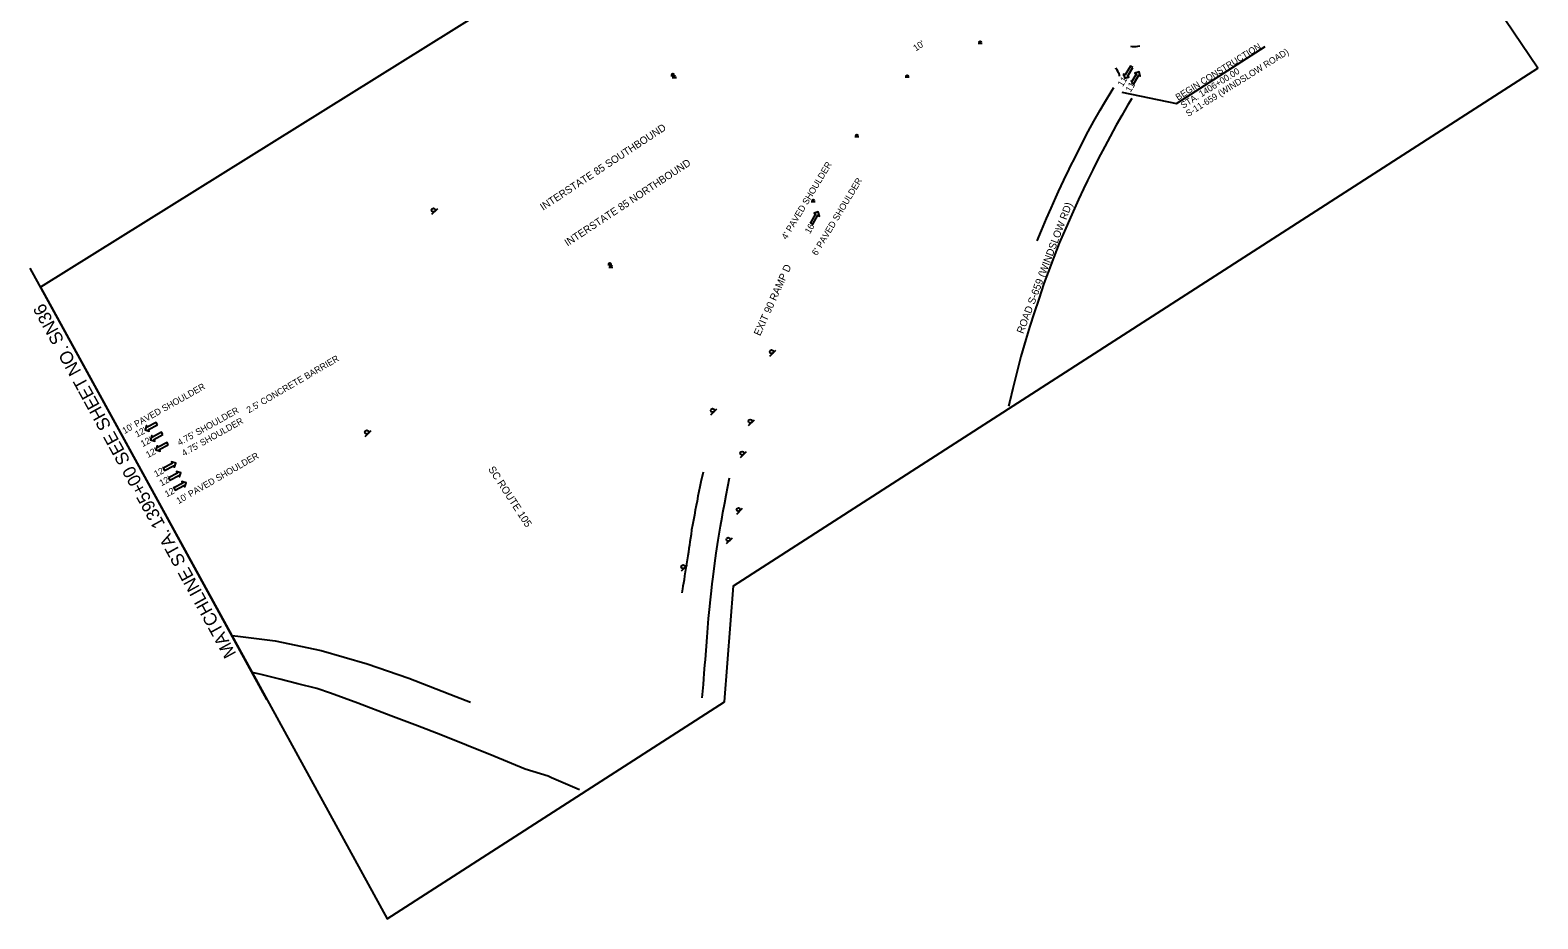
# Model space of a CAD drawing. Extents: x 1788362 to 1789997, y 1182358 to 1184055.
# Drawn here: x 1788362 to 1789997, y 1182358 to 1183321 of the extents above; entities that cross this region are included whole.
import ezdxf

# ---------------------------------------------------------------- set-up
doc = ezdxf.new("R2010")
doc.units = 0
for name, color, linetype in [('RD_EX_Road', 7, 'Continuous'), ('RD_PD_Final_LnLine', 7, 'Continuous'), ('RD_PD_Final_TX', 7, 'Continuous'), ('RD_SHT_MatchLine', 7, 'Continuous'), ('RD_SHT_ShtClip', 7, 'Continuous'), ('RD_TX_RoadID', 7, 'Continuous'), ('SN_P_Signs', 7, 'Continuous')]:
    doc.layers.add(name, color=color, linetype=linetype)

# ---------------------------------------------------------------- blocks, each defined once
blk = doc.blocks.new('SARRW2')
at = {"layer": 'RD_PD_Final_LnLine'}
blk.add_lwpolyline([(-12, 1.2), (-12, -1.2), (-2.8, -1.2), (-2.8, -2.8), (0, 0), (-2.8, 2.8), (-2.8, 1.2)], close=True, dxfattribs=at)

msp = doc.modelspace()

# ---------------------------------------------------------------- linework, layer by layer
at = {"layer": 'RD_EX_Road'}
for points in [[(1789554.8, 1183303.5), (1789556.7, 1183303.2), (1789559.2, 1183303), (1789561.1, 1183303.1), (1789563, 1183303.3), (1789565, 1183303.8)], [(1789543.2, 1183271), (1789543, 1183272), (1789542.6, 1183273.4), (1789542, 1183274.6), (1789541.2, 1183276.4), (1789540.2, 1183278), (1789539.1, 1183279.4), (1789538.9, 1183279.5)], [(1789543.2, 1183271), (1789543, 1183272), (1789542.6, 1183273.4), (1789542, 1183274.6), (1789541.2, 1183276.4), (1789540.2, 1183278), (1789539, 1183279.5)], [(1789453.9, 1183092.5), (1789458.4, 1183103.5), (1789463.9, 1183116.7), (1789468.9, 1183128), (1789474, 1183139.4), (1789477, 1183146.1), (1789482.6, 1183158.1), (1789488.5, 1183170.2), (1789489.9, 1183173.3), (1789494.5, 1183182.2), (1789502.2, 1183197.6), (1789509.2, 1183210.9), (1789515.2, 1183222), (1789522.1, 1183234.1), (1789526.7, 1183241.9), (1789535, 1183255.8), (1789536.8, 1183258.8)], [(1789556.4, 1183246.9), (1789552, 1183239.7), (1789545.4, 1183228.4), (1789539.4, 1183217.8), (1789532.8, 1183205.5), (1789527, 1183194.7), (1789520, 1183181.5), (1789514, 1183169.4), (1789508.2, 1183157.7), (1789504, 1183148.9), (1789498.5, 1183137.1), (1789491.4, 1183121.1), (1789484.9, 1183106.3), (1789477.8, 1183089.8), (1789471.9, 1183074.8), (1789465.8, 1183058.6), (1789461.2, 1183046.1), (1789455.5, 1183029.3), (1789450.6, 1183014.5), (1789445.8, 1183000.1), (1789441.4, 1182985.4), (1789436.2, 1182967.1), (1789431.9, 1182949.9), (1789427.4, 1182932.4), (1789424.1, 1182918.7), (1789422.9, 1182913.3)], [(1789091.7, 1182841.8), (1789089.4, 1182831.1), (1789088.3, 1182826), (1789087.2, 1182820.8), (1789086.1, 1182815.6), (1789085.1, 1182810.5), (1789084.1, 1182805.5), (1789083.1, 1182800.4), (1789082.2, 1182795.2), (1789081.2, 1182789.8), (1789080.2, 1182784.3), (1789079.3, 1182779.1), (1789078.6, 1182774.3), (1789077.9, 1182770.1), (1789077.3, 1182766.3), (1789076.8, 1182762.6), (1789076.3, 1182759), (1789075.7, 1182755.1), (1789075.1, 1182751), (1789074.5, 1182746.7), (1789073.8, 1182742.4), (1789073.1, 1182737.9), (1789072.4, 1182733.6), (1789071.7, 1182729.3), (1789071, 1182725.2), (1789070.4, 1182721.5), (1789069.8, 1182718.2), (1789069.4, 1182715.4), (1789068.5, 1182711)], [(1789090.8, 1182597.1), (1789092, 1182611.5), (1789092.5, 1182617.6), (1789092.7, 1182623.6), (1789093.1, 1182628.2), (1789093.7, 1182633.1), (1789094.2, 1182638.2), (1789094.7, 1182643.7), (1789095.4, 1182653.3), (1789096.1, 1182663), (1789096.9, 1182673.1), (1789097.6, 1182683), (1789098.6, 1182693), (1789099.8, 1182703.3), (1789100.7, 1182713.3), (1789101.7, 1182720.7), (1789102.6, 1182728.2), (1789104.5, 1182743.2), (1789105.9, 1182754.1), (1789108.1, 1182768.1), (1789110.6, 1182783.4), (1789112.2, 1182793), (1789113.2, 1182797.9), (1789115.1, 1182808.4), (1789116.7, 1182816.8), (1789120.4, 1182835.6)], [(1788580.9, 1182664.6), (1788587.2, 1182664), (1788627.7, 1182658.9), (1788677.6, 1182648.4), (1788727.6, 1182634.2), (1788772.6, 1182618.4), (1788823.8, 1182598.6), (1788839.5, 1182592.5)], [(1788957.9, 1182497.6), (1788927.4, 1182510.6), (1788923.7, 1182512.2), (1788898.8, 1182519.8), (1788864.7, 1182534), (1788835.4, 1182545.9), (1788807.3, 1182557.1), (1788782.2, 1182566.8), (1788753.4, 1182577.6), (1788717.4, 1182591.3), (1788687.8, 1182602.2), (1788673, 1182607.2), (1788652.5, 1182612.5), (1788632.8, 1182617.5), (1788612.7, 1182622.4), (1788602.9, 1182624.6)]]:
    msp.add_lwpolyline(points, dxfattribs=at)
at = {"layer": 'RD_PD_Final_TX'}
for p, q in [((1789605, 1183241.4), (1789701.1, 1183303.2)), ((1789545.4, 1183253.6), (1789605, 1183241.4))]:
    msp.add_line(p, q, dxfattribs=at)
at = {"layer": 'RD_SHT_MatchLine'}
msp.add_lwpolyline([(1788618.9, 1182595.5), (1788482.6, 1182843.8), (1788362.3, 1183062.9)], dxfattribs=at)
at = {"layer": 'RD_SHT_ShtClip'}
msp.add_lwpolyline([(1789873, 1183462.7), (1789616.4, 1183843.9), (1789510.9, 1184000.6), (1789102.3, 1183737.7), (1789072.3, 1183540), (1788937.1, 1183533.1), (1788932.8, 1183391.2), (1788373.6, 1183042.3), (1788602.9, 1182624.6), (1788749.4, 1182357.6), (1789114.8, 1182592.7), (1789124.7, 1182718.7), (1789996.5, 1183279.6)], close=True, dxfattribs=at)
at = {"layer": 'SN_P_Signs'}
for p, q in [((1789389.8, 1183306.8), (1789394.3, 1183306.8)), ((1789056.7, 1183271.8), (1789061.2, 1183271.8)), ((1789058.2, 1183269.6), (1789062.7, 1183269.6)), ((1789310.7, 1183270.1), (1789315.2, 1183270.1)), ((1789256.1, 1183205.7), (1789260.6, 1183205.7)), ((1788797.7, 1183121.2), (1788804, 1183127.6)), ((1789208.8, 1183135.1), (1789213.3, 1183135.1)), ((1788988.3, 1183066.7), (1788992.8, 1183066.7)), ((1788989.5, 1183064.1), (1788994, 1183064.1)), ((1789164.1, 1182967.6), (1789170.5, 1182973.9)), ((1789100.1, 1182904), (1789106.5, 1182910.3)), ((1789141, 1182892.2), (1789147.4, 1182898.6)), ((1788725.4, 1182880.4), (1788731.8, 1182886.8)), ((1789132.3, 1182857.7), (1789138.6, 1182864)), ((1789128.2, 1182796.4), (1789134.5, 1182802.8)), ((1789117.2, 1182764.3), (1789123.6, 1182770.6)), ((1789068.3, 1182734.7), (1789074.7, 1182741.1))]:
    msp.add_line(p, q, dxfattribs=at)
for centre, radius in [((1789392.1, 1183307.8), 1), ((1789058.9, 1183272.8), 1), ((1789060.5, 1183270.6), 1), ((1789312.9, 1183271.1), 1), ((1789258.4, 1183206.7), 1), ((1788799.4, 1183125.8), 2), ((1789211.1, 1183136.1), 1), ((1788990.5, 1183067.7), 1), ((1788991.8, 1183065.1), 1), ((1789165.9, 1182972.2), 2), ((1789101.9, 1182908.6), 2), ((1789142.8, 1182896.9), 2), ((1788727.2, 1182885.1), 2), ((1789134, 1182862.3), 2), ((1789129.9, 1182801.1), 2), ((1789119, 1182768.9), 2), ((1789070.1, 1182739.3), 2)]:
    msp.add_circle(centre, radius, dxfattribs=at)

# ---------------------------------------------------------------- block references
at = {"layer": 'RD_PD_Final_LnLine'}
for p, xscale, yscale, rotation in [((1789548.7, 1183268.6), 1.1999999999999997, 1.2000000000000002, -121.00059219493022), ((1789564.4, 1183275.5), 1.1999999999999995, 1.2, 58.99940780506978), ((1789216.6, 1183123.8), 1.1999999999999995, 1.2000000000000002, 60.344883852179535), ((1788486.9, 1182887.7), 1.2000000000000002, 1.2000000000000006, -151.9060440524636), ((1788492.7, 1182876.9), 1.2000000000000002, 1.2000000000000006, -151.9060440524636), ((1788498.6, 1182865.9), 1.2000000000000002, 1.2000000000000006, -151.9060440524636), ((1788520, 1182851.6), 1.2, 1.2000000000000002, 28.093955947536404), ((1788525.6, 1182841.1), 1.2, 1.2000000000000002, 28.093955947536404), ((1788531.3, 1182830.3), 1.2, 1.2000000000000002, 28.093955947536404)]:
    msp.add_blockref('SARRW2', p, dxfattribs=dict(at, xscale=xscale, yscale=yscale, rotation=rotation))

# ---------------------------------------------------------------- texts
at = {"layer": 'RD_PD_Final_TX'}
for s, rotation, p in [("10'", 33.9474, (1789322.3, 1183297.6)), ('BEGIN CONSTRUCTION', 32.1266, (1789606.5, 1183244.4)), ('S-11-659 (WINDSLOW ROAD)', 32.1266, (1789617.6, 1183226.7)), ("11'", 58.9994, (1789546.5, 1183258.9)), ('STA. 1406+00.00', 32.1266, (1789612.1, 1183235.6)), ("11'", 58.9994, (1789555, 1183252.9)), ("4' PAVED SHOULDER", 58.9844, (1789182.1, 1183093.3)), ("6' PAVED SHOULDER", 58.9844, (1789215, 1183075.9)), ("16'", 60.3449, (1789207.5, 1183099.5)), ("2.5' CONCRETE BARRIER", 30.2779, (1788599.3, 1182905.4)), ("10' PAVED SHOULDER", 29.3198, (1788464.6, 1182883)), ("4.75' SHOULDER", 29.3198, (1788524.2, 1182870.2)), ("4.75' SHOULDER", 29.3198, (1788529, 1182858.7)), ("12'", 28.094, (1788478.2, 1182879.2)), ("12'", 28.094, (1788484.3, 1182868.9)), ("12'", 28.094, (1788490, 1182857)), ("10' PAVED SHOULDER", 29.9583, (1788523.2, 1182807)), ("12'", 28.094, (1788498.8, 1182836.2)), ("12'", 28.094, (1788504.6, 1182826.4)), ("12'", 28.094, (1788510.4, 1182814.4))]:
    msp.add_text(s, height=7, rotation=rotation, dxfattribs=at).set_placement(p)
at = {"layer": 'RD_SHT_MatchLine'}
msp.add_text('MATCHLINE STA. 1395+00 SEE SHEET NO. SN36', height=14, rotation=118.7635, dxfattribs=at).set_placement((1788586, 1182645))
at = {"layer": 'RD_TX_RoadID'}
for s, rotation, p in [('INTERSTATE 85 SOUTHBOUND', 33.3541, (1788918.3, 1183125)), ('INTERSTATE 85 NORTHBOUND', 33.4974, (1788944.8, 1183086.2)), ('ROAD S-659 (WINDSLOW RD)', 69.2839, (1789438.7, 1182991.2)), ('EXIT 90 RAMP D', 65.7832, (1789153.5, 1182988.8)), ('SC ROUTE 105', 303.0754, (1788858.4, 1182845))]:
    msp.add_text(s, height=8, rotation=rotation, dxfattribs=at).set_placement(p)

doc.saveas('drawing.dxf')
